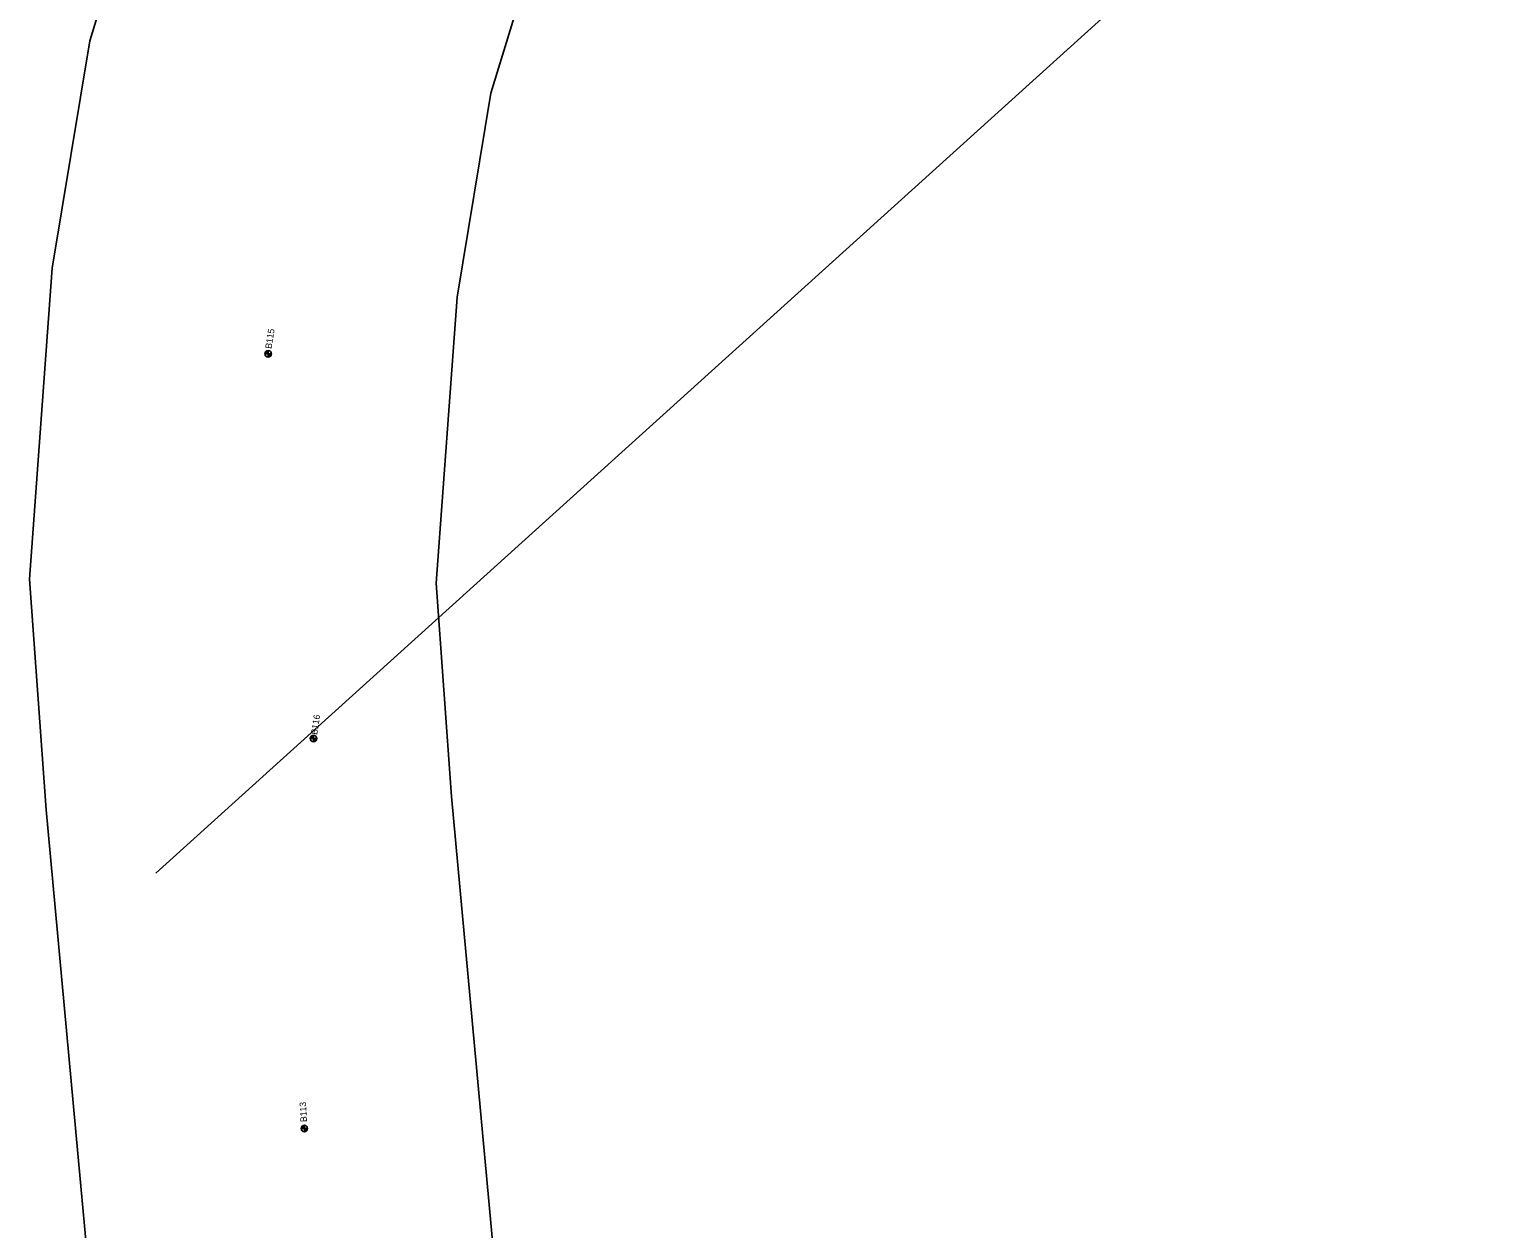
# Model space of a CAD drawing. Extents: x 345549 to 379569, y 127949 to 230467.
# Drawn here: x 354760 to 357051, y 191230 to 193089 of the extents above; entities that cross this region are included whole.
import ezdxf

# ---------------------------------------------------------------- set-up
doc = ezdxf.new("R2010")
doc.units = 0
for name, color, linetype in [('E_SOIL_BORE1 [KAPUR_CADDS_LEVELS]', 7, 'Continuous'), ('E_SOIL_BORE2 [KAPUR_CADDS_LEVELS]', 7, 'Continuous'), ('P_MARK', 7, 'Continuous'), ('P_MISC_TXT', 7, 'Continuous'), ('P_TC', 7, 'Continuous')]:
    doc.layers.add(name, color=color, linetype=linetype)

msp = doc.modelspace()

# ---------------------------------------------------------------- linework, layer by layer
at = {"layer": 'P_MARK'}
for p, q in [((355125.2, 192585.9), (355135.2, 192585.9)), ((355130.2, 192590.9), (355130.2, 192580.9)), ((355195.5, 191989.3), (355205.5, 191989.3)), ((355200.5, 191994.3), (355200.5, 191984.3)), ((355186.3, 191389.7), (355186.3, 191379.7)), ((355181.3, 191384.7), (355191.3, 191384.7))]:
    msp.add_line(p, q, dxfattribs=at)
for centre in [(355130.2, 192585.9), (355200.5, 191989.3), (355186.3, 191384.7)]:
    msp.add_circle(centre, 5, dxfattribs=at)
for centre, radius, start, end in [((355130.2, 192585.9), 4.5, 89.9869, 179.9869), ((355130.2, 192585.9), 4, 89.9869, 179.9869), ((355130.2, 192585.9), 3.5, 89.9869, 179.9869), ((355130.2, 192585.9), 3, 89.9869, 179.9869), ((355130.2, 192585.9), 2.5, 89.9869, 179.9869), ((355130.2, 192585.9), 2, 89.9869, 179.9869), ((355130.2, 192585.9), 1.5, 89.9869, 179.9869), ((355130.2, 192585.9), 1, 89.9869, 179.9869), ((355130.2, 192585.9), 0.5, 89.9869, 179.9869), ((355130.2, 192585.9), 4.5, 269.9869, 359.9869), ((355130.2, 192585.9), 4, 269.9869, 359.9869), ((355130.2, 192585.9), 3.5, 269.9869, 359.9869), ((355130.2, 192585.9), 3, 269.9869, 359.9869), ((355130.2, 192585.9), 2.5, 269.9869, 359.9869), ((355130.2, 192585.9), 2, 269.9869, 359.9869), ((355130.2, 192585.9), 1.5, 269.9869, 359.9869), ((355130.2, 192585.9), 1, 269.9869, 359.9869), ((355130.2, 192585.9), 0.5, 269.9869, 359.9869), ((355200.5, 191989.3), 4.5, 89.9869, 179.9869), ((355200.5, 191989.3), 4, 89.9869, 179.9869), ((355200.5, 191989.3), 3.5, 89.9869, 179.9869), ((355200.5, 191989.3), 3, 89.9869, 179.9869), ((355200.5, 191989.3), 2.5, 89.9869, 179.9869), ((355200.5, 191989.3), 2, 89.9869, 179.9869), ((355200.5, 191989.3), 1.5, 89.9869, 179.9869), ((355200.5, 191989.3), 1, 89.9869, 179.9869), ((355200.5, 191989.3), 0.5, 89.9869, 179.9869), ((355200.5, 191989.3), 4.5, 269.9869, 359.9869), ((355200.5, 191989.3), 4, 269.9869, 359.9869), ((355200.5, 191989.3), 3.5, 269.9869, 359.9869), ((355200.5, 191989.3), 3, 269.9869, 359.9869), ((355200.5, 191989.3), 2.5, 269.9869, 359.9869), ((355200.5, 191989.3), 2, 269.9869, 359.9869), ((355200.5, 191989.3), 1.5, 269.9869, 359.9869), ((355200.5, 191989.3), 1, 269.9869, 359.9869), ((355200.5, 191989.3), 0.5, 269.9869, 359.9869), ((355186.3, 191384.7), 4.5, 89.9869, 179.9869), ((355186.3, 191384.7), 4, 89.9869, 179.9869), ((355186.3, 191384.7), 3.5, 89.9869, 179.9869), ((355186.3, 191384.7), 3, 89.9869, 179.9869), ((355186.3, 191384.7), 2.5, 89.9869, 179.9869), ((355186.3, 191384.7), 2, 89.9869, 179.9869), ((355186.3, 191384.7), 1.5, 89.9869, 179.9869), ((355186.3, 191384.7), 1, 89.9869, 179.9869), ((355186.3, 191384.7), 0.5, 89.9869, 179.9869), ((355186.3, 191384.7), 4.5, 269.9869, 359.9869), ((355186.3, 191384.7), 4, 269.9869, 359.9869), ((355186.3, 191384.7), 3.5, 269.9869, 359.9869), ((355186.3, 191384.7), 3, 269.9869, 359.9869), ((355186.3, 191384.7), 2.5, 269.9869, 359.9869), ((355186.3, 191384.7), 2, 269.9869, 359.9869), ((355186.3, 191384.7), 1.5, 269.9869, 359.9869), ((355186.3, 191384.7), 1, 269.9869, 359.9869), ((355186.3, 191384.7), 0.5, 269.9869, 359.9869)]:
    msp.add_arc(centre, radius, start, end, dxfattribs=at)
at = {"layer": 'P_MISC_TXT'}
msp.add_line((360055.9, 196388.9), (354956.1, 191780.4), dxfattribs=at)
at = {"layer": 'P_TC'}
for points in [[(356152.8, 197292.2), (356212, 196743), (356187.3, 196360.3), (356179.9, 196244.9), (356018.8, 195710.6), (355837.4, 195262), (355656.1, 194887.8), (355482.1, 194535), (355440.2, 194457.1), (355289.7, 194177.8), (355101.7, 193774.2), (354970.8, 193454.6), (354853.6, 193071.5), (354795.4, 192718.8), (354760.1, 192236.5), (354785.6, 191878.7), (354863.4, 191037.4), (354881.9, 190789.8), (354894.4, 190621.4)], [(355623.7, 189359.8), (355599.1, 189703.9), (355561.9, 190209.7), (355523.3, 190642.3), (355513, 190780.1), (355492.2, 191058.8), (355414.4, 191899.6), (355390.9, 192230.2), (355423.4, 192673.7), (355475.5, 192990), (355581.9, 193337.5), (355704.1, 193635.9), (355884.8, 194023.7), (356075.4, 194377.7), (356076.7, 194380.4), (356252.5, 194736.8), (356408.1, 195057.9), (356439.2, 195122), (356624.7, 195580.8), (356805, 196161.9), (356858.4, 196659.7), (356825.6, 197186.3)]]:
    msp.add_lwpolyline(points, dxfattribs=at)

# ---------------------------------------------------------------- texts
at = {"layer": 'E_SOIL_BORE1 [KAPUR_CADDS_LEVELS]'}
msp.add_text('B115', height=10, rotation=80.9358, dxfattribs=at).set_placement((355135.3, 192593.3))
at = {"layer": 'E_SOIL_BORE2 [KAPUR_CADDS_LEVELS]'}
for s, rotation, p in [('B116', 80.9358, (355206.1, 191994.8)), ('B113', 93.0065, (355190.4, 191394.9))]:
    msp.add_text(s, height=10, rotation=rotation, dxfattribs=at).set_placement(p)

doc.saveas('drawing.dxf')
